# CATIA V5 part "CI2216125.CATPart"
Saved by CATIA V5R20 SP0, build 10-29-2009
Part number: CI2216125
Bounding box of the stored display mesh (mm): x -15 to 15, y -10.788 to 149, z -21.241 to 16.291
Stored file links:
  C:\Users\Raffaele\Desktop\3D X SITO CF\BOLEX\19-INCLINED ASSEMBLY REF_CI\CI2216125.CATPart
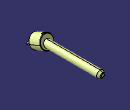
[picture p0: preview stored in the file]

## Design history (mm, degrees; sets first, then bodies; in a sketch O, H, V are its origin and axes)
Set1
  DatumSurface1 to DatumSurface16 "MANIFOLD_SOLID_BREP #385"
  DatumSurface17 to DatumSurface39 "MANIFOLD_SOLID_BREP #1143"
Body1 (main body)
